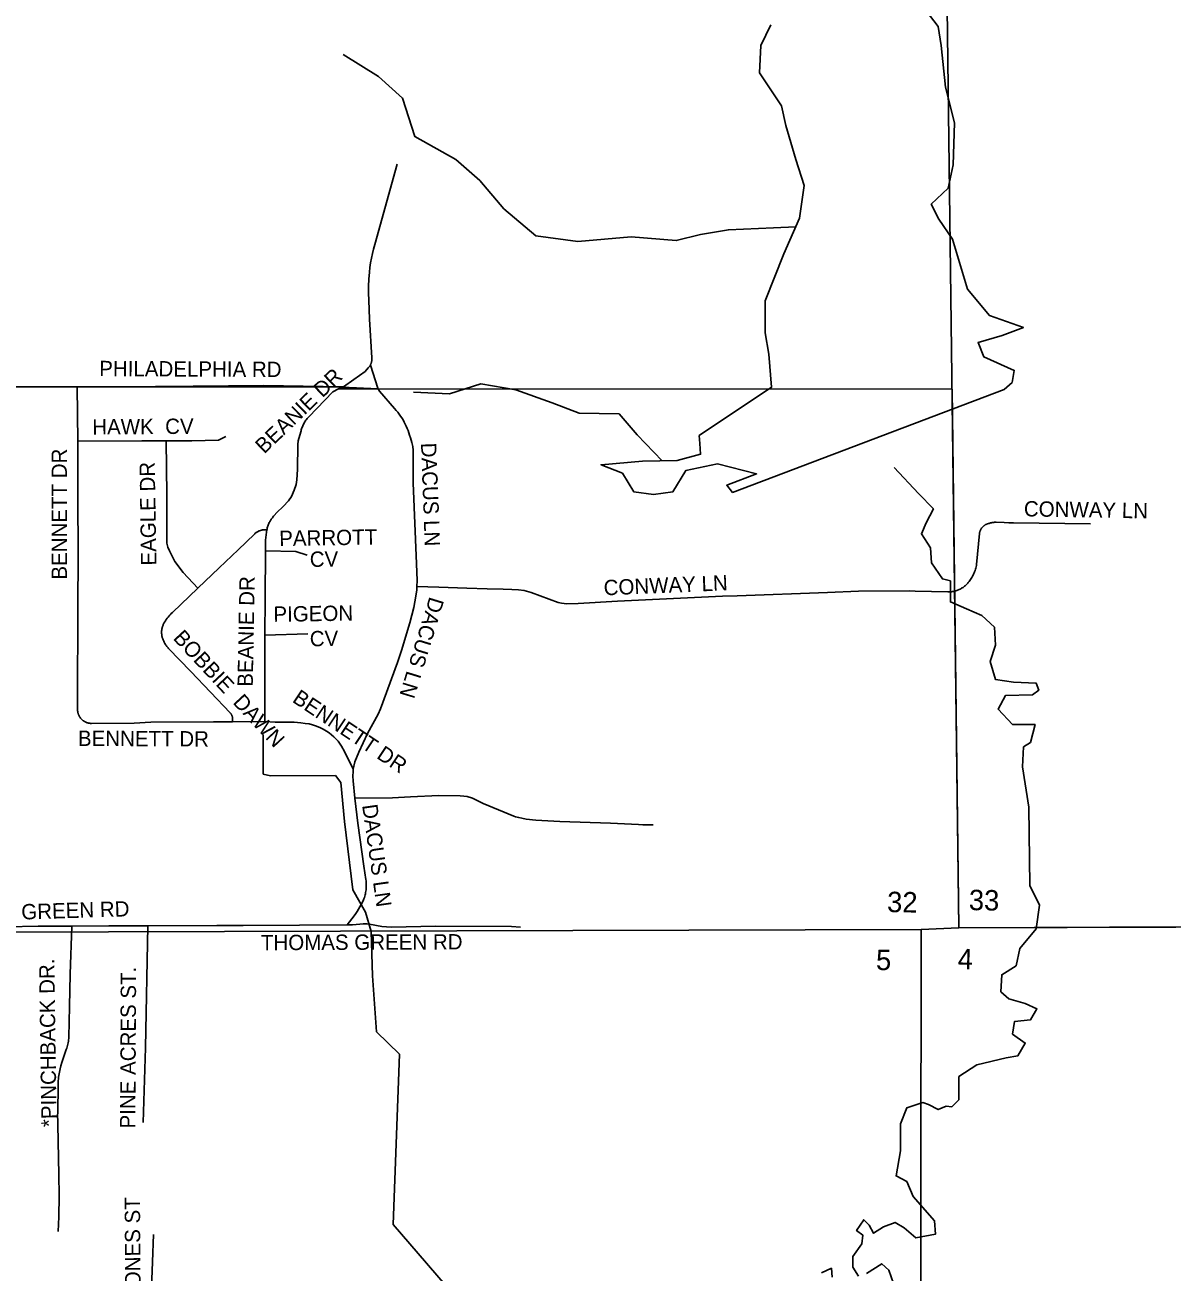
# Model space of a CAD drawing. Extents: x 1670563 to 1761545, y 515755 to 578944.
# Drawn here: x 1700127 to 1705739, y 563544 to 569646 of the extents above; entities that cross this region are included whole.
import ezdxf

# ---------------------------------------------------------------- set-up
doc = ezdxf.new("R2010")
doc.units = 0
for name, color, linetype in [('4_TwnRge', 7, 'Continuous'), ('5_sectionlines', 7, 'Continuous'), ('62_text', 7, 'Continuous'), ('LIMITS', 7, 'Continuous'), ('SHP_LINE', 7, 'Continuous'), ('STREETCL', 7, 'Continuous'), ('STRNAMES', 7, 'Continuous')]:
    doc.layers.add(name, color=color, linetype=linetype)

# ---------------------------------------------------------------- blocks, each defined once
blk = doc.blocks.new('CITY_LIMITS02')
at = {"layer": 'LIMITS'}
blk.add_line((1704662.8, 567864.4), (1704696.7, 565228.3), dxfattribs=at)
for points in [[(1701855.6, 567864.9), (1701678.1, 567873.3), (1700383.3, 567875), (1699392.8, 567874.9)], [(1701855.6, 567864.9), (1704662.8, 567864.4)], [(1704662.8, 567864.4), (1704696.7, 565228.3)], [(1704696.7, 565228.3), (1710001.4, 565245.6)]]:
    blk.add_lwpolyline(points, dxfattribs=at)

msp = doc.modelspace()

# ---------------------------------------------------------------- linework, layer by layer
at = {"layer": '4_TwnRge'}
msp.add_lwpolyline([(1720455.1, 565306), (1715208.3, 565227.8), (1715092.6, 565233.3), (1710001.7, 565251.4), (1709850.1, 565251.4), (1704696.7, 565228.3), (1704511, 565220.7), (1699397.7, 565205.1), (1699224.1, 565203.4), (1693900.8, 565154.5), (1688559.5, 565099.9), (1688483.7, 565104.9), (1683270, 565036.6)], dxfattribs=at)
at = {"layer": '5_sectionlines'}
for points in [[(1704696.7, 565228.3), (1704628.9, 570500.6), (1704634, 572370.1)], [(1704407.6, 557333.3), (1704504.6, 559990.6), (1704511, 565220.7)]]:
    msp.add_lwpolyline(points, dxfattribs=at)
at = {"layer": 'SHP_LINE'}
for points in [[(1704536, 569715), (1704595, 569639), (1704609, 569546), (1704630, 569341), (1704675, 569167), (1704668, 568962), (1704644, 568848), (1704561, 568769), (1704599, 568695), (1704665, 568598), (1704738, 568353), (1704846, 568224), (1705012, 568165), (1704908, 568127), (1704790, 568092), (1704818, 568022), (1704967, 567956), (1704957, 567897), (1704917, 567863)], [(1704917, 567863), (1703589, 567359), (1703561, 567394), (1703707, 567449), (1703516, 567498), (1703360, 567466), (1703297, 567362), (1703203, 567348), (1703106, 567362), (1703050, 567453), (1702946, 567494), (1703148, 567512), (1703318, 567515), (1703433, 567546), (1703429, 567598), (1703426, 567637), (1703780, 567873), (1703767, 568036), (1703749, 568140), (1703749, 568297), (1703840, 568526), (1703916, 568700), (1703940, 568860), (1703899, 568987), (1703850, 569154), (1703829, 569251), (1703721, 569411), (1703728, 569546), (1703777, 569647)], [(1701685, 569502), (1701857, 569394), (1701975, 569287), (1702034, 569100), (1702235, 568988), (1702352, 568885), (1702470, 568747), (1702627, 568615), (1702833, 568586), (1703093, 568610), (1703314, 568591), (1703432, 568620), (1703569, 568644), (1703790, 568654), (1703898, 568659)], [(1703245, 567514), (1703123, 567640), (1703034, 567743), (1702838, 567747), (1702706, 567797), (1702529, 567860), (1702357, 567890), (1702205, 567841), (1702029, 567850)], [(1704205, 563524), (1704178, 563568), (1704178, 563620), (1704222, 563682), (1704226, 563725), (1704196, 563747), (1704231, 563800), (1704257, 563774), (1704279, 563734), (1704327, 563765), (1704384, 563787), (1704428, 563760), (1704485, 563712), (1704582, 563730), (1704577, 563795), (1704472, 563914), (1704441, 563988), (1704389, 564015), (1704411, 564137), (1704411, 564269), (1704441, 564348), (1704520, 564374), (1704547, 564365), (1704595, 564339), (1704634, 564356), (1704661, 564352), (1704696, 564387), (1704696, 564501), (1704784, 564558), (1704928, 564593), (1704985, 564603), (1705021, 564665), (1704959, 564709), (1704968, 564770), (1705047, 564779), (1705078, 564832), (1705021, 564858), (1704941, 564881), (1704902, 564916), (1704906, 564999), (1704977, 565043), (1704994, 565127), (1705074, 565224), (1705091, 565339), (1705043, 565435), (1705038, 565819), (1705007, 566017), (1705012, 566114), (1705047, 566136), (1705069, 566224), (1704959, 566224), (1704888, 566299), (1704924, 566365), (1705056, 566369), (1705087, 566391), (1705074, 566426), (1704963, 566431), (1704875, 566444), (1704849, 566532), (1704875, 566611), (1704871, 566699), (1704809, 566757), (1704733, 566789), (1704655, 566823), (1704655, 566926), (1704616, 566936), (1704562, 567014), (1704557, 567088), (1704513, 567157), (1704537, 567210), (1704572, 567279), (1704498, 567353), (1704380, 567480)], [(1702810, 562640), (1702264, 563388), (1701928, 563777), (1701959, 564611), (1701847, 564720), (1701828, 564994), (1701821, 565211), (1701794, 565305), (1701732, 565415), (1701690, 565748), (1701673, 565940), (1701646, 565974), (1701328, 565973), (1701293, 565981), (1701293, 566175)], [(1704025, 563541), (1704073, 563563), (1704077, 563519)], [(1704376, 563489), (1704354, 563554), (1704319, 563585), (1704244, 563537)]]:
    msp.add_lwpolyline(points, dxfattribs=at)
at = {"layer": 'STREETCL'}
for points in [[(1701947.7, 568964.3), (1701838.9, 568571.5), (1701832.6, 568549.4), (1701827.1, 568527.1), (1701822.4, 568504.7), (1701818.4, 568482.1), (1701815.1, 568459.4), (1701812.6, 568436.6), (1701810, 568402.4), (1701808.5, 568368.3), (1701808.2, 568334), (1701809, 568299.8), (1701812.7, 568206.3), (1701825, 568017.4), (1701825.1, 568015.1), (1701825.1, 568012.8), (1701825.1, 568010.5), (1701825, 568008.2), (1701824.7, 568005.9), (1701824.5, 568003.7), (1701824.1, 568001.4), (1701823.6, 567999.2), (1701823.1, 567996.9), (1701822.5, 567994.7), (1701821.9, 567992.5), (1701821.1, 567990.3), (1701820.3, 567988.2), (1701819.4, 567986.1), (1701818.4, 567984), (1701817.4, 567982)], [(1701817.4, 567982), (1701816.3, 567980), (1701815.2, 567978.2), (1701814, 567976.3), (1701812.8, 567974.5), (1701811.4, 567972.7), (1701810.1, 567971), (1701808.7, 567969.3), (1701807.2, 567967.7), (1701791.2, 567950.5), (1701736, 567910.7), (1701685.5, 567875.8), (1701682.3, 567874.7)], [(1701855.6, 567864.9), (1701853.6, 567868.8), (1701817.4, 567982)], [(1699913.9, 567876.3), (1700106.1, 567875.3), (1700383.3, 567875)], [(1700383.3, 567875), (1700582.2, 567874.8), (1700949.9, 567877.9), (1701296, 567881.6), (1701682.3, 567874.7)], [(1700383.3, 567875), (1700385.8, 567609.9)], [(1701682.3, 567874.7), (1701678.1, 567873.3), (1701661.7, 567864.9)], [(1701661.7, 567864.9), (1701633.9, 567850.6), (1701515.5, 567727.9), (1701511.9, 567724.1), (1701508.5, 567720.2), (1701505.2, 567716.2), (1701502.1, 567712), (1701499.1, 567707.8), (1701496.3, 567703.4), (1701493.6, 567699), (1701491.1, 567694.5), (1701488.7, 567689.8), (1701486.5, 567685.1), (1701484.5, 567680.4), (1701482.6, 567675.5), (1701480.9, 567670.6), (1701479.3, 567665.6), (1701478, 567660.6), (1701476.8, 567655.6), (1701464.5, 567610.9), (1701462.1, 567592.5), (1701460.9, 567470.4), (1701457.8, 567420.2), (1701454.7, 567398.1), (1701444.9, 567369.2), (1701430.7, 567338.6), (1701416.6, 567317.2), (1701390.2, 567289.6), (1701360.2, 567259.9), (1701346.9, 567245.3), (1701343.7, 567241.9), (1701340.6, 567238.4), (1701337.7, 567234.8), (1701334.8, 567231.2), (1701332.2, 567227.4), (1701329.6, 567223.5), (1701327.2, 567219.6), (1701324.9, 567215.5), (1701322.8, 567211.4), (1701320.8, 567207.2), (1701319, 567203), (1701317.3, 567198.7), (1701315.7, 567194.3), (1701314.4, 567189.9), (1701313.1, 567185.4), (1701312.1, 567180.9), (1701311.1, 567176.4)], [(1701661.7, 567864.9), (1701855.6, 567864.9)], [(1702045.2, 566898.2), (1702045.8, 566927.7), (1702042.3, 567008.7), (1702026.5, 567406.3), (1702026.8, 567564.8), (1702024.3, 567583.1), (1702019.9, 567602.8), (1702017.4, 567614.3), (1702014, 567626.1), (1702009.5, 567639), (1702006, 567650.1), (1702002.1, 567661), (1701997.8, 567671.7), (1701993.2, 567682.4), (1701988.2, 567692.8), (1701982.8, 567703.1), (1701977.1, 567713.2), (1701971.1, 567723.1), (1701964.7, 567732.7), (1701958, 567742.2), (1701951, 567751.4), (1701943.7, 567760.4), (1701936, 567769.1), (1701861.3, 567854), (1701855.6, 567864.9)], [(1701110.2, 567632.9), (1701074.9, 567614.5), (1700943.6, 567610.7), (1700818.6, 567611.1)], [(1700385.8, 567609.9), (1700386.2, 567568.2), (1700386.2, 567288.3), (1700388.2, 567103.6), (1700386.9, 566744.2), (1700384.9, 566384.5), (1700384.9, 566296.7), (1700384.9, 566294.4), (1700385.1, 566292), (1700385.3, 566289.7), (1700385.5, 566287.3), (1700385.9, 566285), (1700386.4, 566282.7), (1700386.9, 566280.4), (1700387.5, 566278.1), (1700388.2, 566275.8), (1700388.9, 566273.6), (1700389.8, 566271.4), (1700390.7, 566269.2), (1700391.7, 566267.1), (1700392.8, 566265), (1700393.9, 566262.9), (1700395.1, 566260.9), (1700396.4, 566258.9), (1700397.7, 566257), (1700399.1, 566255.1), (1700400.6, 566253.2), (1700402.2, 566251.4), (1700403.8, 566249.7), (1700405.4, 566248), (1700407.1, 566246.4), (1700408.9, 566244.9), (1700410.7, 566243.4), (1700412.6, 566241.9), (1700414.5, 566240.6), (1700416.5, 566239.3), (1700418.5, 566238), (1700420.6, 566236.9), (1700422.7, 566235.8), (1700424.8, 566234.8), (1700427, 566233.9), (1700429.2, 566233), (1700431.4, 566232.2), (1700433.7, 566231.5), (1700435.9, 566230.9), (1700438.2, 566230.3), (1700440.5, 566229.9), (1700442.9, 566229.5), (1700445.2, 566229.2), (1700447.6, 566228.9), (1700449.9, 566228.8), (1700452.3, 566228.7), (1700661.7, 566229.4), (1700743.6, 566234.7), (1701049.4, 566236.6), (1701143.4, 566237.1)], [(1700818.6, 567611.1), (1700698.6, 567611.4), (1700385.8, 567609.9)], [(1700818.6, 567611.1), (1700821.2, 567347.4), (1700821.2, 567143.3), (1700821.9, 567111.1), (1700825.8, 567091.2), (1700834.2, 567073.5), (1700860.3, 567021.4), (1700901.8, 566966.9), (1700973.8, 566891.1)], [(1702045.2, 566898.2), (1702151.8, 566896), (1702289.2, 566891), (1702389.4, 566887.7), (1702466.8, 566885.4), (1702509.1, 566883.8), (1702542.4, 566882.1), (1702570.3, 566878.2), (1702603.7, 566868.8), (1702736.7, 566819.8), (1702752.8, 566816.5), (1702777.9, 566814.3), (1702833.5, 566815.9), (1703026.6, 566827.6), (1703540.3, 566851), (1703611, 566852.1), (1704052.9, 566869.9), (1704205.9, 566876.1), (1704453, 566877), (1704482.9, 566876.2), (1704643, 566872.4), (1704647.3, 566872.4), (1704651.7, 566872.5), (1704656, 566872.8), (1704660.3, 566873.2), (1704664.7, 566873.8), (1704668.9, 566874.5), (1704673.2, 566875.4), (1704677.4, 566876.4), (1704681.6, 566877.5), (1704685.7, 566878.9), (1704689.8, 566880.3), (1704693.9, 566881.9), (1704697.9, 566883.6), (1704701.8, 566885.5), (1704705.6, 566887.5), (1704709.4, 566889.7), (1704713.1, 566891.9), (1704716.7, 566894.3), (1704720.3, 566896.8), (1704723.7, 566899.5), (1704727.1, 566902.2), (1704730.3, 566905.1), (1704733.5, 566908.1), (1704736.5, 566911.2), (1704739.5, 566914.4), (1704742.3, 566917.7), (1704746.2, 566922.5), (1704749.9, 566927.5), (1704753.4, 566932.6), (1704756.8, 566937.7), (1704760, 566943), (1704763, 566948.4), (1704765.8, 566953.9), (1704768.5, 566959.5), (1704770.9, 566965.2), (1704773.2, 566970.9), (1704775.3, 566976.7), (1704777.2, 566982.6), (1704778.9, 566988.6), (1704780.4, 566994.6), (1704781.7, 567000.6), (1704782.8, 567006.7), (1704796.5, 567158.2), (1704797, 567160.5), (1704797.5, 567162.7), (1704798.1, 567164.9), (1704798.8, 567167.1), (1704799.6, 567169.2), (1704800.4, 567171.4), (1704801.4, 567173.5), (1704802.4, 567175.5), (1704803.4, 567177.6), (1704804.6, 567179.6), (1704805.8, 567181.5), (1704807, 567183.4), (1704808.4, 567185.3), (1704809.8, 567187.1), (1704811.2, 567188.8), (1704812.8, 567190.6), (1704814.3, 567192.2), (1704816, 567193.7), (1704817.8, 567195.1), (1704819.6, 567196.4), (1704821.5, 567197.7), (1704823.3, 567198.9), (1704825.3, 567200), (1704827.2, 567201.1), (1704829.2, 567202.1), (1704831.3, 567203.1), (1704833.3, 567204), (1704835.4, 567204.8), (1704837.5, 567205.5), (1704839.7, 567206.2), (1704841.8, 567206.8), (1704844, 567207.3), (1704847.8, 567208.4), (1704851.5, 567209.4), (1704855.3, 567210.3), (1704859.2, 567211.1), (1704863, 567211.7), (1704866.9, 567212.1), (1704870.8, 567212.5), (1704874.7, 567212.6), (1704878.6, 567212.7), (1704918.4, 567211.1), (1704941.3, 567210.4), (1704964.1, 567210.5), (1705339.8, 567204.6)], [(1701311.1, 567176.4), (1701297.2, 567176.2), (1701294.5, 567175.9), (1701291.8, 567175.5), (1701289.1, 567175), (1701286.4, 567174.4), (1701283.7, 567173.7), (1701281.1, 567173), (1701278.4, 567172.1), (1701275.9, 567171.2), (1701273.3, 567170.1), (1701270.8, 567169), (1701268.3, 567167.8), (1701265.9, 567166.5), (1701263.5, 567165.1), (1701261.2, 567163.6), (1701258.9, 567162.1), (1701256.7, 567160.4), (1701254.5, 567158.7), (1701252.4, 567157), (1701250.4, 567155.1), (1701170.3, 567078.4), (1701077.8, 566990.3), (1700973.8, 566891.1)], [(1701311.1, 567176.4), (1701308.9, 567163.8), (1701307.1, 567151.1), (1701305.8, 567138.4), (1701304.9, 567125.7), (1701304.5, 567112.9), (1701304.2, 567073.8)], [(1701304.2, 567073.8), (1701302.2, 566839.6), (1701301.6, 566659.9)], [(1701508, 567052.5), (1701452.3, 567070.2), (1701304.2, 567073.8)], [(1701733.1, 566004.2), (1701741.4, 566040.6), (1701760.7, 566088.7), (1701803.8, 566179.8), (1701855.2, 566273.6), (1701867, 566299.3), (1701950.7, 566526.4), (1701969.3, 566586.1), (1702010.5, 566720.2), (1702029.2, 566796.2), (1702039.2, 566851.2), (1702043.9, 566882.2), (1702045.2, 566898.2)], [(1700973.8, 566891.1), (1700848.8, 566771.3), (1700843.3, 566766), (1700838.1, 566760.6), (1700833, 566754.9), (1700828.1, 566749.1), (1700823.4, 566743.2), (1700818.9, 566737.1), (1700814.5, 566730.8), (1700810.4, 566724.5), (1700808.7, 566721.6), (1700807.2, 566718.8), (1700805.7, 566715.8), (1700804.3, 566712.9), (1700803, 566709.8), (1700801.8, 566706.8), (1700800.7, 566703.6), (1700799.8, 566700.5), (1700798.9, 566697.3), (1700798.2, 566694.1), (1700797.5, 566690.9), (1700797, 566687.7), (1700796.6, 566684.4), (1700796.3, 566681.1), (1700796.1, 566677.8), (1700796, 566674.6), (1700796, 566671.3), (1700796.2, 566668), (1700796.5, 566664.7), (1700796.8, 566661.4), (1700797.3, 566658.2), (1700797.9, 566655), (1700798.6, 566651.7), (1700799.4, 566648.6), (1700800.4, 566645.4), (1700801.4, 566642.3), (1700802.9, 566638.3), (1700804.5, 566634.3), (1700806.2, 566630.4), (1700808.1, 566626.6), (1700810.1, 566622.8), (1700812.2, 566619.1), (1700814.5, 566615.5), (1700816.9, 566611.9), (1700819.3, 566608.4), (1700821.9, 566605), (1700824.6, 566601.7), (1700827.5, 566598.5), (1700830.4, 566595.4), (1700939.2, 566481.9), (1701131.8, 566280.5), (1701132.8, 566279.2), (1701133.8, 566277.9), (1701134.8, 566276.6), (1701135.7, 566275.3), (1701136.6, 566273.9), (1701137.4, 566272.5), (1701138.1, 566271.1), (1701138.8, 566269.6), (1701139.5, 566268.1), (1701140.1, 566266.6), (1701140.7, 566265.1), (1701141.2, 566263.6), (1701141.7, 566262), (1701142.1, 566260.4), (1701142.4, 566258.8), (1701142.7, 566257.3), (1701143, 566255.6), (1701143.2, 566254), (1701143.3, 566252.4), (1701143.4, 566250.8), (1701143.4, 566249.2), (1701143.4, 566247.6), (1701143.3, 566245.9), (1701143.4, 566237.1)], [(1701301.6, 566659.9), (1701301, 566507.1), (1701301.6, 566237.7)], [(1701510.7, 566667.1), (1701301.6, 566659.9)], [(1701143.4, 566237.1), (1701301.6, 566237.7)], [(1701301.6, 566237.7), (1701351.1, 566235.5), (1701443.9, 566234.3), (1701477.9, 566231.5), (1701499, 566229), (1701517.9, 566226.2), (1701533.5, 566222.4), (1701548.5, 566217.4), (1701561.6, 566212.4), (1701572.8, 566207.5), (1701586.8, 566200.3), (1701603.3, 566190.7), (1701615.4, 566181.9), (1701627.9, 566173.2), (1701638.9, 566163.5), (1701659.8, 566142.6), (1701676.6, 566118.1), (1701690.9, 566091.3), (1701733.1, 566004.2)], [(1701740.7, 565862.2), (1701733, 565948), (1701732.2, 565971.1), (1701732.6, 565994.1), (1701733.1, 566004.2)], [(1701740.7, 565862.2), (1701755.8, 565740.3), (1701785.6, 565529.9), (1701795.5, 565464.4), (1701796.3, 565458.1), (1701796.9, 565451.8), (1701797.3, 565445.5), (1701797.5, 565439.2), (1701797.5, 565432.9), (1701797.3, 565426.6), (1701796.8, 565420.3), (1701796.2, 565414), (1701795.3, 565407.8), (1701794.2, 565401.6), (1701793, 565395.4), (1701791.5, 565389.3), (1701789.8, 565383.2), (1701787.9, 565377.2), (1701785.8, 565371.2), (1701783.5, 565365.3), (1701778.2, 565353.7), (1701772.5, 565342.2), (1701766.4, 565330.9), (1701760, 565319.8), (1701753.3, 565308.9), (1701746.2, 565298.3), (1701738.8, 565287.9), (1701704.2, 565243.1)], [(1701740.7, 565862.2), (1701926, 565864.9), (1702013.7, 565869), (1702152.2, 565875.6), (1702256.9, 565874.4), (1702275.1, 565872.7), (1702290, 565870.7), (1702317.7, 565862.4), (1702369.8, 565837.6), (1702518.3, 565775.1), (1702527.8, 565772.2), (1702543.1, 565768.1), (1702558.8, 565764.4), (1702579.9, 565760.3), (1702626.2, 565756.1), (1702744.5, 565749.1), (1702992.2, 565740), (1703128.3, 565734.2), (1703150.6, 565731.7), (1703201.5, 565732.1)], [(1699316.6, 565212.4), (1699330.3, 565212.4), (1699793.9, 565228.8), (1699881, 565229.6), (1700191.8, 565236.7), (1700357.5, 565237.4)], [(1700357.5, 565237.4), (1700348.4, 565002.5), (1700346.2, 564843.5), (1700342.7, 564694), (1700342.1, 564687.1), (1700341.3, 564680.3), (1700340.3, 564673.5), (1700339.1, 564666.7), (1700337.6, 564660), (1700335.9, 564653.4), (1700334, 564646.8), (1700331.9, 564640.2), (1700329.6, 564633.8), (1700312.8, 564584.3), (1700307.9, 564569), (1700303.5, 564553.6), (1700299.6, 564538), (1700296.3, 564522.4), (1700293.4, 564506.6), (1700292.1, 564497.8), (1700291.1, 564489), (1700290.3, 564480.1), (1700289.8, 564471.3), (1700289.6, 564462.4), (1700289.7, 564453.5), (1700287.6, 564327.6), (1700287.3, 564306.9), (1700287.6, 564286.2), (1700288.5, 564265.5), (1700293.4, 564021.1), (1700294.5, 563917.7), (1700293.4, 563814.3), (1700290.1, 563743.6)], [(1700357.5, 565237.4), (1700538.2, 565238.2), (1700729, 565238.7)], [(1700705.8, 564276.3), (1700716.7, 564640.8), (1700729, 565238.7)], [(1700729, 565238.7), (1701066.8, 565239.6), (1701195.4, 565240.3), (1701470.4, 565241.8), (1701704.2, 565243.1)], [(1701704.2, 565243.1), (1701730, 565243.3), (1701766.3, 565246.4), (1701781.5, 565248.1), (1701799.2, 565248.2), (1701813.1, 565246.7), (1701874, 565234.6), (1701918.6, 565232.2), (1702138, 565237), (1702507.1, 565234.7), (1702551.4, 565231.1)], [(1700743.2, 563378.5), (1700752, 563594.1), (1700757.1, 563728.5)]]:
    msp.add_lwpolyline(points, dxfattribs=at)

# ---------------------------------------------------------------- block references
msp.add_blockref('CITY_LIMITS02', (0, 0), dxfattribs=at)

# ---------------------------------------------------------------- texts
at = {"layer": '62_text'}
for s, rotation, p in [('32', 358.9275, (1704344.4, 565305.8)), ('33', 358.9275, (1704744.3, 565315.4)), ('5', 358.92753, (1704290.2, 565022.2)), ('4', 358.92753, (1704689.6, 565026.7))]:
    msp.add_text(s, height=100, rotation=rotation, dxfattribs=at).set_placement(p)
at = {"layer": 'STRNAMES'}
for s, rotation, p in [('PHILADELPHIA RD', 359.70189, (1700490.7, 567927.8)), ('BEANIE DR', 43.93574, (1701297.9, 567544.2)), ('HAWK  CV', 0.44542, (1700457, 567641.8)), ('BENNETT DR', 90.01971, (1700332.8, 566932.3)), ('DACUS LN', 272.13252, (1702064.7, 567600.7)), ('EAGLE DR', 90.959, (1700771, 567001.6)), ('CONWAY LN', 359.00052, (1705013.7, 567241.9)), ('PARROTT', 0.89243, (1701371.8, 567096.4)), (' CV', 0.89243, (1701493.5, 566993.7)), ('BEANIE DR', 88.90955, (1701241.9, 566407.8)), ('CONWAY LN', 2.36437, (1702960, 566855)), ('DACUS LN', 252.96483, (1702107.2, 566852.3)), ('PIGEON  ', 0.89243, (1701343.5, 566725.5)), ('BOBBIE  DAWN', 312.94971, (1700848.4, 566643.2)), (' CV', 0.89243, (1701493.5, 566605.1)), ('BENNETT DR', 326.30234, (1701430.9, 566336.5)), ('BENNETT DR', 359.70189, (1700386.5, 566118.7)), ('DACUS LN', 278.07265, (1701776.7, 565828.3)), ('THOMAS GREEN RD', 1.73945, (1699653.9, 565255.2)), ('THOMAS GREEN RD', 0.23296, (1701282, 565118.9)), ('*PINCHBACK DR.', 90.81055, (1700282.9, 564254.1)), ('PINE ACRES ST.', 89.70189, (1700667.4, 564246.8)), ('JONES ST', 90.36886, (1700693.4, 563420.2))]:
    msp.add_text(s, height=75, rotation=rotation, dxfattribs=at).set_placement(p)

doc.saveas('drawing.dxf')
